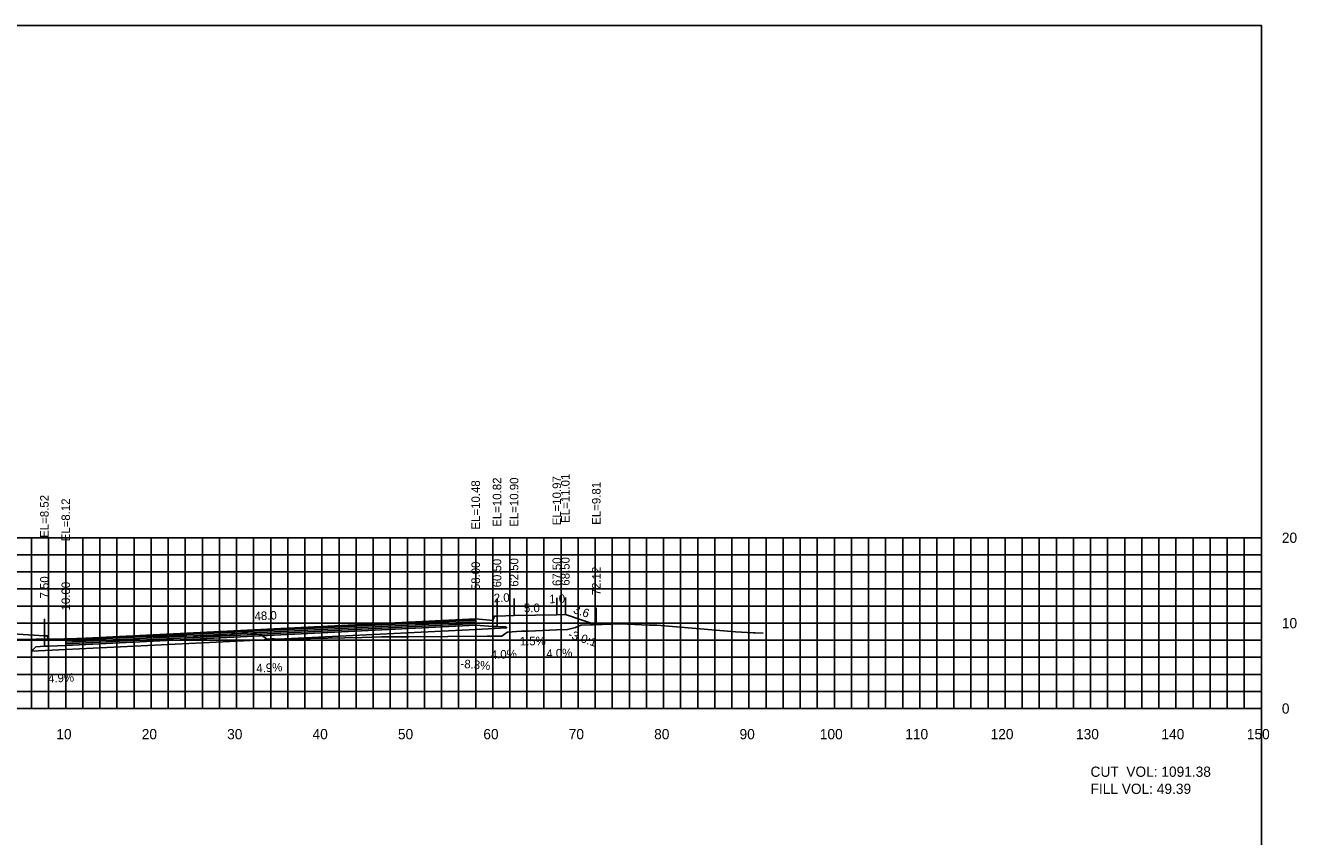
# Model space of a CAD drawing. Extents: x 1797419 to 1809236, y 248759 to 251512.
# Drawn here: x 1805696.3 to 1805845.1, y 250174.4 to 250269.4 of the extents above; entities that cross this region are included whole.
import ezdxf

# ---------------------------------------------------------------- set-up
doc = ezdxf.new("R2010")
doc.units = 0
for name, color, linetype in [('10', 7, 'Continuous'), ('3', 7, 'Continuous'), ('31', 7, 'Continuous'), ('4', 7, 'Continuous'), ('60', 7, 'Continuous'), ('ANNO-TXT', 7, 'Continuous'), ('BASE', 7, 'Continuous'), ('CL-CNST', 7, 'Continuous'), ('Level 62', 7, 'Continuous'), ('LOWER BINDER', 7, 'Continuous'), ('M-ROADS', 7, 'Continuous'), ('UPPER BINDER', 7, 'Continuous'), ('WEARING', 7, 'Continuous')]:
    doc.layers.add(name, color=color, linetype=linetype)

msp = doc.modelspace()

# ---------------------------------------------------------------- linework, layer by layer
for p, q in [((1805749, 250199.92), (1805749, 250201.92)), ((1805751.5, 250200.25), (1805751.5, 250202.25)), ((1805751.51, 250200.25), (1805751.51, 250202.25)), ((1805753.5, 250200.33), (1805753.5, 250202.33)), ((1805758.5, 250200.4), (1805758.5, 250202.4)), ((1805759.5, 250200.44), (1805759.5, 250202.44)), ((1805763.12, 250199.24), (1805763.12, 250201.24)), ((1805698.5, 250197.95), (1805698.5, 250199.95)), ((1805701, 250197.55), (1805701, 250199.55))]:
    msp.add_line(p, q)
for points in [[(1805541, 250079.43), (1805841, 250079.43), (1805841, 250269.43), (1805541, 250269.43)], [(1805749, 250199.92), (1805751, 250199.75), (1805751.17, 250200.25), (1805751.5, 250200.25), (1805751.5, 250199.04), (1805751, 250199.04), (1805749, 250199.2)], [(1805698.5, 250197.95), (1805698.83, 250197.95), (1805699, 250197.45), (1805701, 250197.55), (1805701, 250196.83), (1805699, 250196.73), (1805698.5, 250196.73)]]:
    msp.add_lwpolyline(points, close=True)
at = {"layer": '60'}
for p, q in [((1805841, 250189.43), (1805841, 250209.43)), ((1805841.06, 250209.43), (1805841, 250209.43)), ((1805841.06, 250199.43), (1805841, 250199.43)), ((1805541, 250189.43), (1805841, 250189.43)), ((1805701, 250189.37), (1805701, 250189.43)), ((1805711, 250189.37), (1805711, 250189.43)), ((1805721, 250189.37), (1805721, 250189.43)), ((1805731, 250189.37), (1805731, 250189.43)), ((1805741, 250189.37), (1805741, 250189.43)), ((1805751, 250189.37), (1805751, 250189.43)), ((1805761, 250189.37), (1805761, 250189.43)), ((1805771, 250189.37), (1805771, 250189.43)), ((1805781, 250189.37), (1805781, 250189.43)), ((1805791, 250189.37), (1805791, 250189.43)), ((1805801, 250189.37), (1805801, 250189.43)), ((1805811, 250189.37), (1805811, 250189.43)), ((1805821, 250189.37), (1805821, 250189.43)), ((1805831, 250189.37), (1805831, 250189.43)), ((1805841, 250189.37), (1805841, 250189.43)), ((1805841.06, 250189.43), (1805841, 250189.43))]:
    msp.add_line(p, q, dxfattribs=at)
at = {"layer": 'BASE'}
msp.add_lwpolyline([(1805701, 250196.83), (1805749, 250199.2), (1805751, 250199.04), (1805751.5, 250199.04), (1805752.5, 250199.01), (1805752.64, 250198.88), (1805749, 250198.7), (1805701, 250196.33), (1805696.99, 250196.13), (1805697.5, 250196.65), (1805698.5, 250196.73), (1805699, 250196.73)], close=True, dxfattribs=at)
at = {"layer": 'CL-CNST'}
msp.add_lwpolyline([(1805691, 250198.43), (1805698.5, 250197.95), (1805698.83, 250197.95), (1805699, 250197.45), (1805700.23, 250197.51), (1805701, 250197.55), (1805749, 250199.92), (1805751, 250199.75), (1805751.15, 250200.18), (1805751.17, 250200.25), (1805751.5, 250200.25), (1805751.51, 250200.25), (1805753.5, 250200.33), (1805758.5, 250200.4), (1805759.5, 250200.44), (1805761.57, 250199.75), (1805763.12, 250199.24)], dxfattribs=at)
at = {"layer": 'Level 62'}
for p, q in [((1805541, 250209.43), (1805841, 250209.43)), ((1805697, 250189.43), (1805697, 250209.43)), ((1805699, 250189.43), (1805699, 250209.43)), ((1805701, 250189.43), (1805701, 250209.43)), ((1805703, 250189.43), (1805703, 250209.43)), ((1805705, 250189.43), (1805705, 250209.43)), ((1805707, 250189.43), (1805707, 250209.43)), ((1805709, 250189.43), (1805709, 250209.43)), ((1805711, 250189.43), (1805711, 250209.43)), ((1805713, 250189.43), (1805713, 250209.43)), ((1805715, 250189.43), (1805715, 250209.43)), ((1805717, 250189.43), (1805717, 250209.43)), ((1805719, 250189.43), (1805719, 250209.43)), ((1805721, 250189.43), (1805721, 250209.43)), ((1805723, 250189.43), (1805723, 250209.43)), ((1805725, 250189.43), (1805725, 250209.43)), ((1805727, 250189.43), (1805727, 250209.43)), ((1805729, 250189.43), (1805729, 250209.43)), ((1805731, 250189.43), (1805731, 250209.43)), ((1805733, 250189.43), (1805733, 250209.43)), ((1805735, 250189.43), (1805735, 250209.43)), ((1805737, 250189.43), (1805737, 250209.43)), ((1805739, 250189.43), (1805739, 250209.43)), ((1805741, 250189.43), (1805741, 250209.43)), ((1805743, 250189.43), (1805743, 250209.43)), ((1805745, 250189.43), (1805745, 250209.43)), ((1805747, 250189.43), (1805747, 250209.43)), ((1805749, 250189.43), (1805749, 250209.43)), ((1805751, 250189.43), (1805751, 250209.43)), ((1805753, 250189.43), (1805753, 250209.43)), ((1805755, 250189.43), (1805755, 250209.43)), ((1805757, 250189.43), (1805757, 250209.43)), ((1805759, 250189.43), (1805759, 250209.43)), ((1805761, 250189.43), (1805761, 250209.43)), ((1805763, 250189.43), (1805763, 250209.43)), ((1805765, 250189.43), (1805765, 250209.43)), ((1805767, 250189.43), (1805767, 250209.43)), ((1805769, 250189.43), (1805769, 250209.43)), ((1805771, 250189.43), (1805771, 250209.43)), ((1805773, 250189.43), (1805773, 250209.43)), ((1805775, 250189.43), (1805775, 250209.43)), ((1805777, 250189.43), (1805777, 250209.43)), ((1805779, 250189.43), (1805779, 250209.43)), ((1805781, 250189.43), (1805781, 250209.43)), ((1805783, 250189.43), (1805783, 250209.43)), ((1805785, 250189.43), (1805785, 250209.43)), ((1805787, 250189.43), (1805787, 250209.43)), ((1805789, 250189.43), (1805789, 250209.43)), ((1805791, 250189.43), (1805791, 250209.43)), ((1805793, 250189.43), (1805793, 250209.43)), ((1805795, 250189.43), (1805795, 250209.43)), ((1805797, 250189.43), (1805797, 250209.43)), ((1805799, 250189.43), (1805799, 250209.43)), ((1805801, 250189.43), (1805801, 250209.43)), ((1805803, 250189.43), (1805803, 250209.43)), ((1805805, 250189.43), (1805805, 250209.43)), ((1805807, 250189.43), (1805807, 250209.43)), ((1805809, 250189.43), (1805809, 250209.43)), ((1805811, 250189.43), (1805811, 250209.43)), ((1805813, 250189.43), (1805813, 250209.43)), ((1805815, 250189.43), (1805815, 250209.43)), ((1805817, 250189.43), (1805817, 250209.43)), ((1805819, 250189.43), (1805819, 250209.43)), ((1805821, 250189.43), (1805821, 250209.43)), ((1805823, 250189.43), (1805823, 250209.43)), ((1805825, 250189.43), (1805825, 250209.43)), ((1805827, 250189.43), (1805827, 250209.43)), ((1805829, 250189.43), (1805829, 250209.43)), ((1805831, 250189.43), (1805831, 250209.43)), ((1805833, 250189.43), (1805833, 250209.43)), ((1805835, 250189.43), (1805835, 250209.43)), ((1805837, 250189.43), (1805837, 250209.43)), ((1805839, 250189.43), (1805839, 250209.43)), ((1805841, 250189.43), (1805841, 250209.43)), ((1805541, 250207.43), (1805841, 250207.43)), ((1805541, 250205.43), (1805841, 250205.43)), ((1805541, 250203.43), (1805841, 250203.43)), ((1805541, 250201.43), (1805841, 250201.43)), ((1805541, 250199.43), (1805841, 250199.43)), ((1805541, 250197.43), (1805841, 250197.43)), ((1805541, 250195.43), (1805841, 250195.43)), ((1805541, 250193.43), (1805841, 250193.43)), ((1805541, 250191.43), (1805841, 250191.43)), ((1805541, 250189.43), (1805841, 250189.43))]:
    msp.add_line(p, q, dxfattribs=at)
at = {"layer": 'LOWER BINDER'}
for points in [[(1805701, 250197.21), (1805749, 250199.58), (1805749, 250199.39), (1805701, 250197.02)], [(1805701, 250197.02), (1805749, 250199.39), (1805749, 250199.2), (1805701, 250196.83)]]:
    msp.add_lwpolyline(points, close=True, dxfattribs=at)
at = {"layer": 'M-ROADS'}
msp.add_lwpolyline([(1805690.72, 250197.45), (1805697.52, 250197.56), (1805700.87, 250197.6), (1805712.33, 250197.89), (1805712.54, 250197.9), (1805713.17, 250197.9), (1805716.12, 250197.96), (1805716.19, 250197.96), (1805716.41, 250197.96), (1805717.34, 250197.98), (1805717.84, 250197.99), (1805720.16, 250197.94), (1805720.21, 250197.98), (1805720.21, 250197.98), (1805720.21, 250197.99), (1805720.22, 250197.97), (1805720.27, 250197.98), (1805720.27, 250197.99), (1805720.28, 250197.99), (1805720.28, 250197.99), (1805720.28, 250197.98), (1805720.3, 250197.96), (1805720.31, 250197.98), (1805720.31, 250198), (1805720.32, 250198.01), (1805720.33, 250198.03), (1805720.33, 250198.03), (1805720.34, 250198.05), (1805720.34, 250198.06), (1805720.35, 250198.08), (1805720.36, 250198.08), (1805720.38, 250198.07), (1805720.38, 250198.1), (1805720.4, 250198.09), (1805720.43, 250198.06), (1805720.44, 250198.12), (1805720.46, 250198.19), (1805720.47, 250198.26), (1805720.49, 250198.21), (1805720.54, 250198.1), (1805720.55, 250198.09), (1805720.6, 250198.02), (1805720.62, 250198.06), (1805720.62, 250198.06), (1805720.63, 250198.04), (1805720.66, 250198.17), (1805720.66, 250198.2), (1805720.69, 250198.36), (1805720.7, 250198.44), (1805720.71, 250198.38), (1805720.72, 250198.33), (1805720.73, 250198.29), (1805720.74, 250198.34), (1805720.75, 250198.35), (1805720.76, 250198.38), (1805720.77, 250198.39), (1805720.77, 250198.37), (1805720.78, 250198.37), (1805720.79, 250198.36), (1805720.79, 250198.36), (1805720.93, 250198.5), (1805721.4, 250198.45), (1805723.85, 250198.07), (1805723.98, 250197.98), (1805724.49, 250197.6), (1805725.02, 250197.57), (1805725.03, 250197.58), (1805725.04, 250197.59), (1805725.06, 250197.59), (1805725.07, 250197.59), (1805725.1, 250197.58), (1805725.11, 250197.58), (1805725.12, 250197.6), (1805725.14, 250197.59), (1805725.15, 250197.58), (1805725.18, 250197.59), (1805725.23, 250197.59), (1805725.23, 250197.59), (1805725.25, 250197.59), (1805725.28, 250197.59), (1805725.3, 250197.59), (1805725.34, 250197.59), (1805725.4, 250197.58), (1805725.41, 250197.58), (1805725.44, 250197.56), (1805725.5, 250197.56), (1805725.6, 250197.55), (1805725.61, 250197.54), (1805725.67, 250197.53), (1805725.72, 250197.55), (1805725.76, 250197.56), (1805725.87, 250197.55), (1805725.96, 250197.54), (1805726.92, 250197.56), (1805729.65, 250197.62), (1805735.72, 250197.76), (1805737.98, 250197.81), (1805741.12, 250197.84), (1805750.35, 250197.91), (1805750.43, 250197.91), (1805750.47, 250197.91), (1805750.56, 250197.9), (1805750.66, 250197.89), (1805750.73, 250197.88), (1805750.75, 250197.88), (1805750.83, 250197.89), (1805750.91, 250197.9), (1805750.92, 250197.9), (1805750.97, 250197.9), (1805751.03, 250197.9), (1805752.08, 250197.89), (1805752.53, 250198.25), (1805752.74, 250198.39), (1805754.34, 250198.49), (1805754.47, 250198.49), (1805754.78, 250198.49), (1805754.8, 250198.49), (1805755.16, 250198.49), (1805755.17, 250198.49), (1805758.46, 250198.64), (1805759.75, 250198.7), (1805760.69, 250198.91), (1805761.3, 250199.19), (1805762.42, 250199.22), (1805762.59, 250199.23), (1805762.75, 250199.23), (1805765.92, 250199.33), (1805769.3, 250199.21), (1805769.35, 250199.21), (1805770, 250199.21), (1805770.2, 250199.21), (1805770.21, 250199.21), (1805779.43, 250198.43), (1805781.48, 250198.29), (1805781.54, 250198.29), (1805781.74, 250198.29), (1805782.65, 250198.24)], dxfattribs=at)
at = {"layer": 'UPPER BINDER'}
msp.add_lwpolyline([(1805701, 250197.4), (1805749, 250199.77), (1805749, 250199.58), (1805701, 250197.21)], close=True, dxfattribs=at)
at = {"layer": 'WEARING'}
msp.add_lwpolyline([(1805701, 250197.55), (1805749, 250199.92), (1805749, 250199.77), (1805701, 250197.4)], close=True, dxfattribs=at)

# ---------------------------------------------------------------- texts
msp.add_text('-3.0:1', height=1, rotation=341.5598).set_placement((1805759.74, 250197.73))
at = {"layer": '10'}
for s, p in [('10', (1805699.9, 250185.83)), ('20', (1805709.9, 250185.83)), ('30', (1805719.9, 250185.83)), ('40', (1805729.9, 250185.83)), ('50', (1805739.9, 250185.83)), ('60', (1805749.9, 250185.83)), ('70', (1805759.9, 250185.83)), ('80', (1805769.9, 250185.83)), ('90', (1805779.9, 250185.83)), ('100', (1805789.3, 250185.83)), ('110', (1805799.3, 250185.83)), ('120', (1805809.3, 250185.83)), ('130', (1805819.3, 250185.83)), ('140', (1805829.3, 250185.83)), ('150', (1805839.3, 250185.83))]:
    msp.add_text(s, height=1.2, dxfattribs=at).set_placement(p)
at = {"layer": '3'}
for s, p in [('EL=10.97', (1805759, 250210.88)), ('EL=11.01', (1805760, 250211.17)), ('EL=10.48', (1805749.5, 250210.39)), ('EL=10.82', (1805752, 250210.72)), ('EL=10.82', (1805752.01, 250210.72)), ('EL=10.90', (1805754, 250210.72)), ('EL=9.81', (1805763.62, 250210.95)), ('EL=8.52', (1805699, 250209.42)), ('EL=8.12', (1805701.5, 250209.01)), ('58.00', (1805749.5, 250203.29)), ('60.50', (1805752, 250203.62)), ('62.50', (1805754, 250203.7)), ('67.50', (1805759, 250203.78)), ('68.50', (1805760, 250203.82)), ('7.50', (1805699, 250202.31)), ('72.12', (1805763.62, 250202.69)), ('10.00', (1805701.5, 250200.92))]:
    msp.add_text(s, height=1, rotation=90, dxfattribs=at).set_placement(p)
at = {"layer": '31'}
for s, p in [('20', (1805843.4, 250208.83)), ('10', (1805843.4, 250198.83)), ('0', (1805843.4, 250188.83))]:
    msp.add_text(s, height=1.2, dxfattribs=at).set_placement(p)
at = {"layer": '4'}
for s, rotation, p in [('2.0', 2.2909, (1805751.14, 250201.87)), ('5.0', 0.8594, (1805754.66, 250200.7)), ('1.0', 2.2885, (1805757.63, 250201.75)), ('48.0', 2.8219, (1805723.13, 250199.74)), ('3.6', 341.5598, (1805760.35, 250200.63)), ('1.5%', 0.8594, (1805754.16, 250196.81)), ('4.0%', 2.2909, (1805750.79, 250195.22)), ('4.0%', 2.2885, (1805757.29, 250195.35)), ('4.9%', 2.8219, (1805723.34, 250193.64)), ('-8.3%', 355.2546, (1805747.19, 250194.21)), ('4.9%', 2.8057, (1805698.95, 250192.44))]:
    msp.add_text(s, height=1, rotation=rotation, dxfattribs=at).set_placement(p)
at = {"layer": 'ANNO-TXT'}
for s, p in [('CUT  VOL: 1091.38', (1805821, 250181.43)), ('FILL VOL: 49.39', (1805821, 250179.43))]:
    msp.add_text(s, height=1.2, dxfattribs=at).set_placement(p)

doc.saveas('drawing.dxf')
